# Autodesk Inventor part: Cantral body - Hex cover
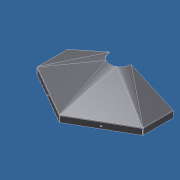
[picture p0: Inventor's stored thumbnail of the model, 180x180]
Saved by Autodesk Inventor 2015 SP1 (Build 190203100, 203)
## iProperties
Category: Mechanical Engineering Drawing and Design - CADD
Manager: Fábio Ricardo de Oliveira Souza
Company: SENAI - Serviço Nacional de Aprendizagem Industrial
Created: 2011-06
Part Number: Cantral body - Hex cover
Material: Steel
Description: Stainless Steel (DIN- X6NiCrTi18-10)
Document SubType Name: Sheet Metal
Designer: Guilherme Augusto Franco de Souza
Engineer: George Geraldo de Oliveia Silva
Authority: Fábio Ricardo de Oliveira Soza
Density: 7.85 g/cm^3
Sheet Metal Rule: Default_mm
Flat Pattern Width: 34.4825 cm
Flat Pattern Length: 49.4888 cm
Flat Pattern Area: 1706.5 cm^2
Sheet Metal Width: 344,825 mm
Sheet Metal Length: 494,888 mm
Sheet Metal Area: 170649,746 mm^2
Appearance: Machined 02
Subject: WorldSkill 2011 - London, England
Author: Guilherme Augusto Franco de Souza
Revision Number: 00
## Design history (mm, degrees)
sketch "Sketch1"
  geometry: L1 (0, 244.797)-(212, 122.398); L2 (212, 122.398)-(212, -122.398); L3 (212, -122.398)-(0, -244.797); L4 (0, -244.797)-(-212, -122.398); L5 (-212, -122.398)-(-212, 122.398); L6 (-212, 122.398)-(0, 244.797); 2 further points
  constraints: 12 end point, 1 coincident, 1 vertical alignment, 13 other
  dimensions: "d0" = 424 distance between parallel lines of L2 L5
workplane "Work Plane1"
node "Lofted Flange1"
  sketch "Sketch2"
    geometry: C1 r 42.5 at (0, 0); 1 further point
    constraints: 1 centre point, 1 coincident
    dimensions: "d2" = 85 diameter of C1
split "Split1"
node "Flange1"
node "Unfold5"
sketch "Sketch4"
  geometry: L1 (-1.866, 0)-(-2.064, -2.161); L2 (-1.965, -1.08)-(-2.271, -1.052); L3 (215.618, -42.334)-(92.319, -223.922) reference; L4 (92.319, -223.922)-(91.271, -225.465) reference; L5 (92.948, -226.843)-(94.259, -225.515) reference; L6 (94.259, -225.515)-(248.465, -69.32) reference; L7 (248.465, -69.32)-(329.432, -273.332) reference; L8 (329.432, -273.332)-(330.12, -275.067) reference; L9 (332.201, -274.453)-(331.839, -272.623) reference; L10 (331.839, -272.623)-(289.243, -57.304) reference; L11 (91.271, -225.465)-(92.948, -226.843); L12 (92.109, -226.154)-(91.914, -226.391); L13 (330.12, -275.067)-(332.201, -274.453); L14 (331.161, -274.76)-(331.248, -275.055); C1 r 3 at (-2.271, -1.052); C2 r 3 at (331.248, -275.055); C3 r 3 at (91.914, -226.391); 1 further point
  constraints: 12 end point, 3 centre point, 3 coincident, 3 midpoint, 3 perpendicular, 8 other
  dimensions: "d18" = 6 diameter of C1 (= d20); "d19" = 6 diameter of C2 (= d20); "d20" = 6 diameter of C3
cut "Cut1" sketch "Sketch4" dims "d21" = 1.2 (= Thickness), "d22" = 0
node "Refold9"
sketch "Sketch5"
  geometry: L1 (242.025, 0)-(0, 0) reference; 2 further points
  constraints: 1 vertical alignment
  dimensions: "d23" = 10 distance from line of L1 point (121.013, 10)
hole "Hole1" sketch "Sketch5" at (121.013, 10) diameter "d24" = 6.6; stored, may be unused: countersink angle "d28" = 90 deg, drill point angle "d30" = 118 deg; dims "d25" = 6, "d26" = 18, "d27" = 4.8, "d29" = 1.2 (= Thickness)
mirror "Mirror1"
workplane "Work Plane2"
split "Split2"
body "Solid1"
bend "Bend1" dims "d3" = 1.2 (= BendRadius), "d4" = 1.2 (= BendReliefWidth), "d5" = 0.6 (= BendReliefDepth), "d6" = 2.4 (= MinimumRemnant), "d7" = 1.2 (= BendRadius), "SeamGap" = 0.01, "Thickness" = 1.2 (derived)
sketch "Sketch3"
  geometry: L1 through (121.013, 0) direction (-1, -1.61e-17); L2 through (0, -12.5) direction (2.46e-16, -1); L3 (0, -25)-(242.025, -25); L4 (242.025, -25)-(242.025, 0)
  constraints: 6 end point, 1 horizontal, 1 perpendicular, 1 vertical
face "Plate1" dims "d8" = 1.2 (= BendReliefWidth), "d9" = 0.6 (= BendReliefDepth), "d10" = 2.4 (= MinimumRemnant), "d11" = 1.2 (= BendRadius), "d12" = 25, "d13" = 11.54186, "d14" = 1.2 (= BendRadius), "d15" = 4.8 (= CornerReliefSize), "d16" = 0.6 (= 0.5 x GapSize), "d17" = 1.2 (= JacobiRadiusSize), "SeamGap" = 0.01, "Thickness" = 1.2 (derived)
bend "Bend2" dims "d8" = 1.2 (= BendReliefWidth), "d9" = 0.6 (= BendReliefDepth), "d10" = 2.4 (= MinimumRemnant), "d11" = 1.2 (= BendRadius), "d12" = 25, "d13" = 11.54186, "d14" = 1.2 (= BendRadius), "SeamGap" = 0.01, "Thickness" = 1.2 (derived)
feature "Corner1" dims "d12" = 25, "d13" = 11.54186, "d15" = 4.8 (= CornerReliefSize), "d16" = 0.6 (= 0.5 x GapSize), "d17" = 1.2 (= JacobiRadiusSize)
node "Projected Loop1"
node "Projected Loop2"
feature "Definition1"
feature "Cosmetic Centerline1" dims "d9" = 1.2 (= BendRadius), "d10" = 150 deg, "Thickness" = 1.2 (derived)
other parameters: "BendRadius" = 1.2 (= Thickness), "BendReliefWidth" = 1.2 (= Thickness), "BendReliefDepth" = 0.6 (= 0.5 x Thickness), "CornerReliefSize" = 4.8 (= 4 x Thickness), "MinimumRemnant" = 2.4 (= 2 x Thickness), "TransitionRadius" = 1.2 (= BendRadius), "JacobiRadiusSize" = 1.2 (= BendRadius), "GapSize" = 1.2 (= Thickness), "d1" = 75, "d60" = -0.5, "BendRadius" = 1.2, "BendReliefDepth" = 0.6, "BendReliefWidth" = 1.2, "CornerReliefSize" = 4.8, "GapSize" = 1.2, "JacobiRadiusSize" = 1.2, "MinimumRemnant" = 2.4, "Thickness" = 1.2, "TransitionRadius" = 1.2, "d0" = 2.60813 (derived), "d1" = 1.30407 (= 0.5 x d0), "d2" = 1.82496 (derived), "d3" = 0.91248 (= 0.5 x d2), "d5" = 1.30407 (= d1), "d6" = 0.91248 (= d3), "d7" = 1.30407 (= d5), "d8" = 0.91248 (= d6)
